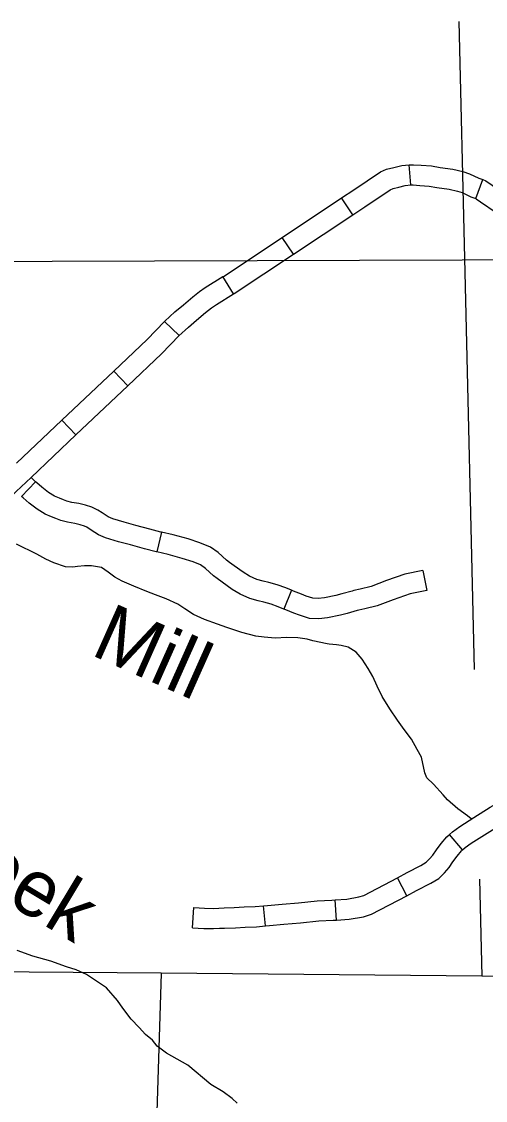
# Model space of a CAD drawing. Extents: x -492261 to -432772, y 1441225 to 1452922.
# Drawn here: x -463667.5 to -463569.5, y 1451714.7 to 1451942.8 of the extents above; entities that cross this region are included whole.
import ezdxf

# ---------------------------------------------------------------- set-up
doc = ezdxf.new("R2010")
doc.units = 0
doc.layers.add('Default', color=7, linetype='Continuous')

msp = doc.modelspace()

# ---------------------------------------------------------------- linework, layer by layer
at = {"layer": 'Default'}
for p, q in [((-463585.2, 1451908.28), (-463585.59, 1451912.55)), ((-463571.51, 1451905.41), (-463569.99, 1451909.41)), ((-463597.46, 1451901.96), (-463599.83, 1451905.53)), ((-463610.04, 1451893.62), (-463612.41, 1451897.2)), ((-463622.68, 1451885.26), (-463624.92, 1451888.91)), ((-463634.19, 1451876.43), (-463637.28, 1451879.4)), ((-463645.03, 1451865.81), (-463647.98, 1451868.92)), ((-463655.98, 1451855.43), (-463658.93, 1451858.54)), ((-463664.51, 1451845.53), (-463667.47, 1451842.43)), ((-463637.9, 1451834.87), (-463638.88, 1451830.7)), ((-463582.66, 1451826.74), (-463581.83, 1451822.54)), ((-463610.43, 1451822.58), (-463612.08, 1451818.62)), ((-463574.28, 1451767.71), (-463577.06, 1451770.97)), ((-463586.06, 1451758.01), (-463588.06, 1451761.8)), ((-463600.95, 1451752.87), (-463601.23, 1451757.15)), ((-463631.32, 1451751.23), (-463631.05, 1451755.51)), ((-463615.91, 1451751.62), (-463616.33, 1451755.89))]:
    msp.add_line(p, q, dxfattribs=at)
for points in [[(-463575.09, 1451942.83), (-463573.9, 1451892.82), (-463571.8, 1451805.81)], [(-463599.83, 1451905.53), (-463597.29, 1451907.22), (-463591.63, 1451911.05), (-463590.33, 1451911.6), (-463588.8, 1451912.01), (-463587.14, 1451912.41), (-463585.59, 1451912.55)], [(-463585.59, 1451912.55), (-463585.48, 1451912.56), (-463584.63, 1451912.57), (-463583, 1451912.47), (-463580.81, 1451912.31), (-463579.02, 1451911.97), (-463576.36, 1451911.6), (-463574.24, 1451911.12), (-463572.81, 1451910.66), (-463570.87, 1451909.75), (-463569.99, 1451909.41)], [(-463597.46, 1451901.96), (-463594.9, 1451903.66), (-463589.57, 1451907.27), (-463588.94, 1451907.54), (-463587.74, 1451907.85), (-463586.44, 1451908.17), (-463585.2, 1451908.28)], [(-463585.26, 1451908.28), (-463584.74, 1451908.28), (-463583.28, 1451908.19), (-463581.36, 1451908.05), (-463579.72, 1451907.74), (-463577.13, 1451907.38), (-463575.36, 1451906.98), (-463574.39, 1451906.67), (-463572.55, 1451905.8), (-463571.51, 1451905.41)], [(-463569.99, 1451909.41), (-463569.39, 1451909.18), (-463568.02, 1451908.25), (-463564.96, 1451906.12), (-463563.11, 1451905.13), (-463561.36, 1451904.03), (-463559.81, 1451903.27), (-463556.95, 1451902.11), (-463556.7, 1451901.99)], [(-463612.41, 1451897.2), (-463599.83, 1451905.53)], [(-463571.51, 1451905.41), (-463571.39, 1451905.36), (-463570.46, 1451904.72), (-463567.2, 1451902.46), (-463565.27, 1451901.43), (-463563.45, 1451900.28), (-463561.56, 1451899.36), (-463558.7, 1451898.19), (-463558.58, 1451898.13)], [(-463610.04, 1451893.62), (-463597.46, 1451901.96)], [(-463624.92, 1451888.91), (-463624.83, 1451888.96), (-463612.41, 1451897.2)], [(-463392.57, 1451892.71), (-463574.35, 1451892.37), (-463726.12, 1451891.89), (-463873.94, 1451891.93), (-464028.1, 1451891.74), (-464177.92, 1451891.72)], [(-463622.68, 1451885.26), (-463622.53, 1451885.35), (-463610.04, 1451893.62)], [(-463637.28, 1451879.4), (-463637.23, 1451879.46), (-463635.06, 1451881.44), (-463633.28, 1451882.97), (-463631.31, 1451884.64), (-463629.89, 1451885.73), (-463628.66, 1451886.61), (-463624.92, 1451888.91)], [(-463634.23, 1451876.39), (-463632.22, 1451878.23), (-463630.5, 1451879.71), (-463628.62, 1451881.3), (-463627.33, 1451882.29), (-463626.29, 1451883.04), (-463622.68, 1451885.26)], [(-463647.98, 1451868.92), (-463640.91, 1451875.63), (-463637.28, 1451879.4)], [(-463645.03, 1451865.81), (-463637.89, 1451872.59), (-463634.19, 1451876.43)], [(-463658.93, 1451858.54), (-463647.98, 1451868.92)], [(-463655.98, 1451855.43), (-463645.03, 1451865.81)], [(-463668.52, 1451849.45), (-463658.93, 1451858.54)], [(-463665.47, 1451846.44), (-463655.98, 1451855.43)], [(-463677.9, 1451834.69), (-463668.58, 1451843.49), (-463665.47, 1451846.44)], [(-463664.51, 1451845.53), (-463665.47, 1451846.44)], [(-463651.36, 1451839.51), (-463651.62, 1451839.69), (-463652.61, 1451840.13), (-463653.97, 1451840.59), (-463655.38, 1451840.9), (-463656.82, 1451841.16), (-463657.88, 1451841.43), (-463658.59, 1451841.71), (-463659.47, 1451842.08), (-463660.48, 1451842.52), (-463661.75, 1451843.29), (-463663.17, 1451844.37), (-463664.28, 1451845.31), (-463664.51, 1451845.53)], [(-463653.68, 1451835.91), (-463654.18, 1451836.14), (-463655.11, 1451836.45), (-463656.22, 1451836.69), (-463657.75, 1451836.97), (-463659.2, 1451837.35), (-463660.21, 1451837.74), (-463661.17, 1451838.15), (-463662.45, 1451838.71), (-463664.16, 1451839.74), (-463665.85, 1451841.03), (-463667.15, 1451842.12), (-463667.47, 1451842.43)], [(-463637.9, 1451834.87), (-463638.01, 1451834.89), (-463640.37, 1451835.49), (-463643.33, 1451836.31), (-463645.82, 1451836.96), (-463648.22, 1451837.68), (-463649.16, 1451838.11), (-463650.46, 1451838.93), (-463651.36, 1451839.51)], [(-463638.88, 1451830.7), (-463639.02, 1451830.73), (-463641.46, 1451831.34), (-463644.44, 1451832.17), (-463646.98, 1451832.83), (-463649.74, 1451833.66), (-463651.21, 1451834.34), (-463652.77, 1451835.32), (-463653.7, 1451835.93)], [(-463623.53, 1451828.47), (-463624.14, 1451828.94), (-463625.95, 1451830.55), (-463627.56, 1451831.72), (-463629.77, 1451832.63), (-463632.3, 1451833.44), (-463635.41, 1451834.29), (-463637.9, 1451834.87)], [(-463572.46, 1451774.25), (-463573.23, 1451774.91), (-463575.3, 1451776.37), (-463577.49, 1451778.3), (-463578.41, 1451779.37), (-463580.43, 1451781.58), (-463581.81, 1451782.94), (-463582.22, 1451783.96), (-463582.94, 1451787.33), (-463583.87, 1451788.92), (-463585.09, 1451791.14), (-463586.6, 1451793.12), (-463588.04, 1451795.11), (-463589.66, 1451797.49), (-463591.29, 1451800.16), (-463592.34, 1451802.33), (-463593.27, 1451804.38), (-463594.26, 1451806.08), (-463595.53, 1451808.01), (-463596.75, 1451809.49), (-463598.47, 1451810.55), (-463599.96, 1451810.94), (-463600.93, 1451811.04), (-463602.47, 1451811.19), (-463602.87, 1451811.25), (-463605.9, 1451811.9), (-463607.1, 1451812.23), (-463609.1, 1451812.55), (-463611.44, 1451812.58), (-463613.89, 1451812.44), (-463616.23, 1451812.7), (-463618, 1451812.91), (-463620.92, 1451813.67), (-463624.06, 1451814.72), (-463626.07, 1451815.45), (-463628.82, 1451816.44), (-463631.16, 1451817.45), (-463633, 1451818.69), (-463634.44, 1451819.64), (-463636.9, 1451820.76), (-463639.14, 1451821.59), (-463640.97, 1451822.31), (-463643.72, 1451823.43), (-463646.24, 1451824.54), (-463647.73, 1451825.38), (-463649.17, 1451826.45), (-463650.6, 1451827.41), (-463652.72, 1451827.79), (-463654.2, 1451827.77), (-463655.62, 1451827.58), (-463656.65, 1451827.46), (-463658.19, 1451827.55), (-463660.65, 1451828.38), (-463662.31, 1451829.17), (-463664.26, 1451830.23), (-463668.51, 1451832.36)], [(-463626.16, 1451825.09), (-463626.88, 1451825.65), (-463628.63, 1451827.2), (-463629.66, 1451827.95), (-463631.24, 1451828.6), (-463633.52, 1451829.33), (-463636.46, 1451830.13), (-463638.88, 1451830.7)], [(-463610.43, 1451822.58), (-463611.66, 1451823.09), (-463613.45, 1451823.75), (-463615.25, 1451824.22), (-463616.43, 1451824.49), (-463617.75, 1451824.87), (-463619.28, 1451825.59), (-463620.67, 1451826.4), (-463622.57, 1451827.72), (-463623.53, 1451828.47)], [(-463582.66, 1451826.74), (-463586.51, 1451825.98), (-463590.37, 1451824.62), (-463593.57, 1451823.42), (-463595.95, 1451822.85), (-463597.23, 1451822.53)], [(-463612.08, 1451818.62), (-463613.22, 1451819.1), (-463614.74, 1451819.66), (-463616.27, 1451820.06), (-463617.49, 1451820.34), (-463619.26, 1451820.84), (-463621.28, 1451821.79), (-463622.98, 1451822.78), (-463625.11, 1451824.27), (-463626.16, 1451825.09)], [(-463597.23, 1451822.53), (-463597.64, 1451822.42), (-463599.82, 1451821.82), (-463601.06, 1451821.48), (-463603.43, 1451820.98), (-463604.78, 1451820.87), (-463605.9, 1451820.89), (-463607.3, 1451821.33), (-463608.32, 1451821.75), (-463610.03, 1451822.41), (-463610.43, 1451822.58)], [(-463581.83, 1451822.54), (-463585.38, 1451821.84), (-463588.91, 1451820.6), (-463592.31, 1451819.32), (-463594.93, 1451818.69), (-463596.18, 1451818.37)], [(-463596.18, 1451818.37), (-463596.54, 1451818.28), (-463598.68, 1451817.69), (-463600.05, 1451817.31), (-463602.81, 1451816.73), (-463604.65, 1451816.58), (-463606.61, 1451816.63), (-463608.75, 1451817.29), (-463609.91, 1451817.77), (-463611.63, 1451818.44), (-463612.08, 1451818.62)], [(-463577.06, 1451770.97), (-463576.4, 1451771.53), (-463574.85, 1451772.67), (-463571.9, 1451774.52), (-463568.45, 1451776.71), (-463564.68, 1451778.77), (-463563.72, 1451779.2)], [(-463574.28, 1451767.71), (-463573.73, 1451768.18), (-463572.44, 1451769.13), (-463569.61, 1451770.89), (-463566.27, 1451773.02), (-463566.09, 1451773.11)], [(-463588.06, 1451761.8), (-463586, 1451762.89), (-463583.11, 1451764.38), (-463581.96, 1451765.09), (-463581.24, 1451765.78), (-463580.54, 1451766.6), (-463579.79, 1451767.7), (-463578.79, 1451769.03), (-463577.63, 1451770.48), (-463577.06, 1451770.97)], [(-463586.06, 1451758.01), (-463584.02, 1451759.09), (-463581, 1451760.64), (-463579.32, 1451761.68), (-463578.12, 1451762.84), (-463577.13, 1451763.99), (-463576.31, 1451765.2), (-463575.4, 1451766.4), (-463574.53, 1451767.49), (-463574.28, 1451767.71)], [(-463601.23, 1451757.15), (-463598.77, 1451757.3), (-463596.22, 1451757.75), (-463595.12, 1451758.07), (-463588.06, 1451761.8)], [(-463570.73, 1451761.54), (-463570.24, 1451741.01)], [(-463616.33, 1451755.89), (-463615.47, 1451755.97), (-463612.37, 1451756.24), (-463608.93, 1451756.5), (-463605.02, 1451756.95), (-463601.89, 1451757.1), (-463601.23, 1451757.15)], [(-463600.95, 1451752.87), (-463598.27, 1451753.04), (-463595.24, 1451753.57), (-463593.5, 1451754.08), (-463586.06, 1451758.01)], [(-463631.05, 1451755.51), (-463628.81, 1451755.37), (-463627, 1451755.33), (-463625.78, 1451755.4), (-463624.67, 1451755.42), (-463622.51, 1451755.5), (-463620.46, 1451755.63), (-463618.09, 1451755.72), (-463616.33, 1451755.89)], [(-463615.91, 1451751.62), (-463615.08, 1451751.7), (-463612.02, 1451751.97), (-463608.52, 1451752.24), (-463604.67, 1451752.68), (-463601.65, 1451752.82), (-463600.95, 1451752.87)], [(-463631.32, 1451751.23), (-463628.99, 1451751.08), (-463626.92, 1451751.05), (-463625.63, 1451751.12), (-463624.57, 1451751.13), (-463622.29, 1451751.22), (-463620.24, 1451751.35), (-463617.81, 1451751.44), (-463615.91, 1451751.62)], [(-463642.63, 1451730.13), (-463644.3, 1451731.88), (-463646.04, 1451734.21), (-463647.2, 1451735.85), (-463649.51, 1451738.52), (-463653.76, 1451741.33), (-463655.93, 1451742.33), (-463657.99, 1451743), (-463661.26, 1451744.16), (-463665.09, 1451745.21), (-463668.41, 1451746.43)], [(-463488.48, 1451740.87), (-463488.62, 1451740.87), (-463570.24, 1451741.01), (-463637.99, 1451741.6), (-463721.71, 1451742.25), (-463790.72, 1451742.44), (-463871.93, 1451743.32), (-463940.94, 1451743.22), (-464024.61, 1451743.76), (-464093.84, 1451743.89), (-464175.97, 1451744.2), (-464245.72, 1451743.53), (-464326.02, 1451741.84), (-464344.74, 1451741.73)], [(-463637.99, 1451741.6), (-463640.85, 1451648.99), (-463640.73, 1451498.55), (-463640.72, 1451494.02)], [(-463621.93, 1451714.12), (-463622.97, 1451715.13), (-463624.87, 1451716.54), (-463627.45, 1451718.06), (-463632.34, 1451722.18), (-463636.87, 1451724.7), (-463638.83, 1451726.22), (-463639.81, 1451727.47), (-463641.25, 1451728.66), (-463642.63, 1451730.13)]]:
    msp.add_lwpolyline(points, dxfattribs=at)

# ---------------------------------------------------------------- texts
for s, rotation, p in [('Mill', 336, (-463653.15, 1451809.06)), ('Creek', 329, (-463693.19, 1451770.04))]:
    msp.add_text(s, height=12.069, rotation=rotation, dxfattribs=at).set_placement(p)

doc.saveas('drawing.dxf')
